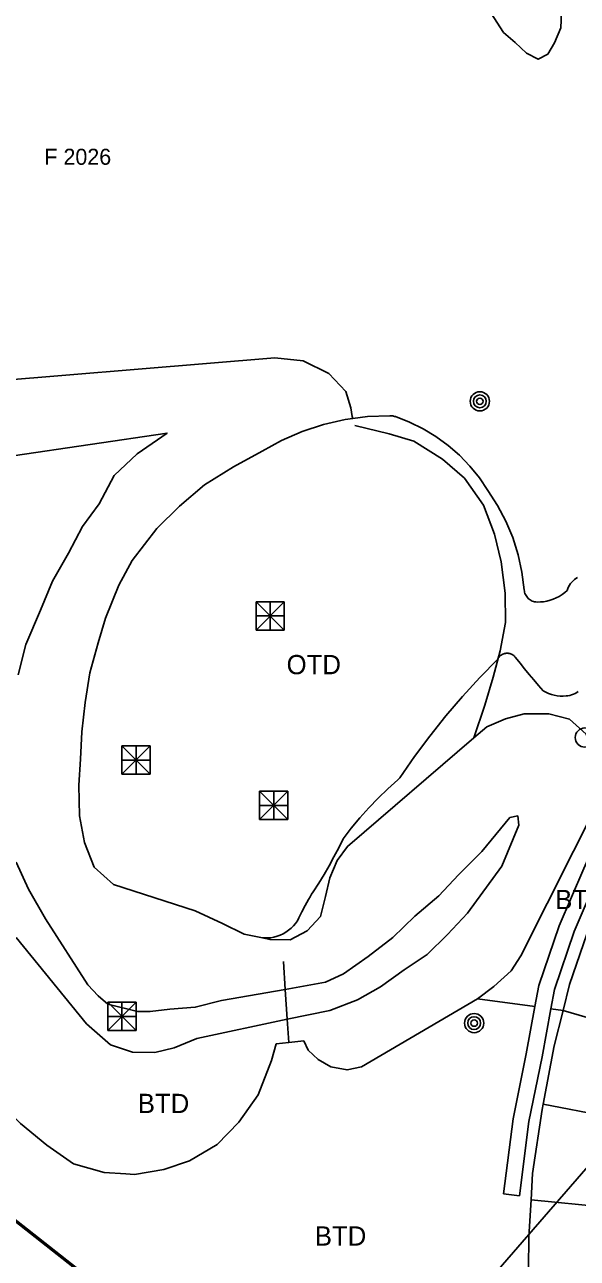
# Model space of a CAD drawing. Extents: x 198240 to 198429, y 356553 to 356721.
# Drawn here: x 198326.68 to 198343.9, y 356600.62 to 356639.08 of the extents above; entities that cross this region are included whole.
import ezdxf

# ---------------------------------------------------------------- set-up
doc = ezdxf.new("R2010")
doc.units = 0
for name, color, linetype in [('begroeid terreindeel kenmerkpunt', 7, 'Continuous'), ('BOOM', 7, 'Continuous'), ('cultuurscheiding geen IMGeo', 7, 'Continuous'), ('Duiker lijn niveau min 1', 7, 'Continuous'), ('grens individueel parkeervak', 7, 'Continuous'), ('Grens maaiveld', 7, 'Continuous'), ('kant verharding', 7, 'Continuous'), ('onbegroeid terreindeel kenmerkpunt', 7, 'Continuous'), ('Perceelnummer', 7, 'Continuous'), ('perceelsgrens_definitief', 7, 'Continuous'), ('Speelvoorziening', 7, 'Continuous')]:
    doc.layers.add(name, color=color, linetype=linetype)

msp = doc.modelspace()

# ---------------------------------------------------------------- linework, layer by layer
at = {"layer": 'BOOM'}
for centre, radius in [((198340.862, 356627.334), 0.3), ((198340.862, 356627.334), 0.2), ((198340.862, 356627.334), 0.1), ((198344.134, 356616.852), 0.3), ((198340.684, 356607.949), 0.3), ((198340.684, 356607.949), 0.2), ((198340.684, 356607.949), 0.1)]:
    msp.add_circle(centre, radius, dxfattribs=at)
at = {"layer": 'cultuurscheiding geen IMGeo'}
msp.add_lwpolyline([(198336.966, 356626.584), (198338.038, 356626.321), (198338.802, 356626.09), (198339.696, 356625.535), (198340.387, 356624.936), (198340.975, 356624.096), (198341.316, 356623.195), (198341.526, 356622.331), (198341.646, 356621.352), (198341.663, 356620.441), (198341.491, 356619.56), (198341.278, 356618.732), (198341.019, 356617.863), (198340.669, 356616.839)], dxfattribs=at)
at = {"layer": 'Duiker lijn niveau min 1'}
msp.add_lwpolyline([(198334.909, 356607.345), (198334.86, 356608.067), (198334.797, 356609), (198334.738, 356609.871)], dxfattribs=at)
at = {"layer": 'grens individueel parkeervak'}
for p, q in [((198347.785, 356607.073), (198343.457, 356608.344)), ((198347.261, 356604.556), (198342.832, 356605.425))]:
    msp.add_line(p, q, dxfattribs=at)
at = {"layer": 'Grens maaiveld'}
msp.add_line((198341.598, 356602.626), (198342.094, 356602.562), dxfattribs=at)
for points in [[(198341.203, 356639.447), (198341.598, 356638.833), (198341.961, 356638.517), (198342.319, 356638.185), (198342.68, 356638), (198342.983, 356638.157), (198343.186, 356638.51), (198343.389, 356638.974), (198343.402, 356639.466)], [(198336.899, 356626.798), (198336.881, 356626.857), (198336.843, 356627.128), (198336.681, 356627.641), (198336.15, 356628.206), (198335.359, 356628.591), (198334.475, 356628.685), (198323.691, 356627.793)], [(198336.899, 356626.798), (198336.668, 356626.767), (198335.987, 356626.612), (198335.324, 356626.394), (198334.684, 356626.116), (198334.073, 356625.779), (198333.185, 356625.294), (198332.277, 356624.73), (198331.505, 356624.068), (198330.796, 356623.364), (198330.024, 356622.371), (198329.607, 356621.601), (198329.195, 356620.573), (198328.969, 356619.801), (198328.711, 356618.869), (198328.561, 356617.945), (198328.457, 356617.025), (198328.414, 356616.174), (198328.359, 356615.367), (198328.382, 356614.413), (198328.537, 356613.584), (198328.844, 356612.812), (198329.442, 356612.27), (198331.985, 356611.454), (198332.837, 356611.057), (198333.516, 356610.723), (198334.034, 356610.613)], [(198336.899, 356626.798), (198337.36, 356626.859), (198338.057, 356626.886), (198338.087, 356626.885), (198338.116, 356626.883), (198338.146, 356626.878), (198338.175, 356626.873), (198338.204, 356626.865), (198338.233, 356626.857), (198338.671, 356626.688), (198339.093, 356626.481), (198339.495, 356626.238), (198339.875, 356625.961), (198340.228, 356625.652), (198340.554, 356625.313), (198340.848, 356624.947), (198341.109, 356624.557), (198341.414, 356624.09), (198341.674, 356623.598), (198341.889, 356623.084), (198342.057, 356622.552), (198342.175, 356622.008), (198342.244, 356621.455), (198342.249, 356621.418), (198342.257, 356621.381), (198342.268, 356621.345), (198342.283, 356621.31), (198342.3, 356621.277), (198342.321, 356621.245), (198342.345, 356621.216), (198342.371, 356621.189), (198342.399, 356621.164), (198342.43, 356621.142), (198342.463, 356621.123), (198342.497, 356621.107), (198342.532, 356621.094), (198342.569, 356621.085), (198342.606, 356621.079), (198342.644, 356621.076), (198342.747, 356621.078), (198342.85, 356621.087), (198342.952, 356621.105), (198343.052, 356621.131), (198343.15, 356621.165), (198343.245, 356621.206), (198343.336, 356621.254), (198343.423, 356621.31), (198343.506, 356621.372), (198343.583, 356621.441), (198343.603, 356621.496), (198343.627, 356621.55), (198343.655, 356621.601), (198343.688, 356621.65), (198343.725, 356621.695), (198343.766, 356621.737), (198343.81, 356621.776), (198343.857, 356621.81), (198343.907, 356621.84)], [(198347.91, 356619.599), (198346.861, 356617.91), (198345.941, 356616.427), (198344.929, 356614.639), (198344.101, 356612.773), (198343.329, 356610.981), (198342.7, 356609.121), (198342.579, 356608.462)], [(198343.93, 356618.292), (198343.881, 356618.259), (198343.83, 356618.229), (198343.777, 356618.204), (198343.722, 356618.183), (198343.666, 356618.167), (198343.608, 356618.155), (198343.55, 356618.147), (198343.457, 356618.142), (198343.364, 356618.144), (198343.272, 356618.154), (198343.18, 356618.17), (198343.091, 356618.194), (198343.003, 356618.225), (198342.918, 356618.262), (198342.836, 356618.306), (198342.689, 356618.477), (198342.544, 356618.648), (198342.399, 356618.821), (198342.256, 356618.995), (198342.114, 356619.17), (198341.973, 356619.346), (198341.956, 356619.368), (198341.938, 356619.388), (198341.917, 356619.407), (198341.895, 356619.424), (198341.872, 356619.438), (198341.847, 356619.451), (198341.821, 356619.462), (198341.795, 356619.47), (198341.768, 356619.476), (198341.74, 356619.48), (198341.712, 356619.481), (198341.685, 356619.48), (198341.657, 356619.476), (198341.63, 356619.47), (198341.604, 356619.462), (198341.578, 356619.451), (198341.553, 356619.439), (198341.53, 356619.424), (198341.508, 356619.407), (198341.487, 356619.388), (198341.468, 356619.368), (198341.451, 356619.346), (198341.436, 356619.322), (198341.424, 356619.298), (198340.864, 356618.724), (198340.323, 356618.133), (198339.802, 356617.524), (198339.302, 356616.898), (198338.822, 356616.256), (198338.364, 356615.599), (198338.355, 356615.586), (198338.346, 356615.574), (198338.336, 356615.562), (198338.325, 356615.55), (198338.314, 356615.539), (198338.302, 356615.529), (198337.991, 356615.251), (198337.69, 356614.962), (198337.4, 356614.661), (198337.122, 356614.35), (198336.856, 356614.028), (198336.602, 356613.697), (198336.462, 356613.413), (198336.316, 356613.133), (198336.164, 356612.856), (198336.006, 356612.582), (198335.841, 356612.312), (198335.671, 356612.046), (198335.62, 356611.964), (198335.57, 356611.882), (198335.521, 356611.799), (198335.416, 356611.612), (198335.317, 356611.423), (198335.224, 356611.231), (198335.174, 356611.142), (198335.116, 356611.059), (198335.051, 356610.98), (198334.979, 356610.908), (198334.901, 356610.842), (198334.818, 356610.784), (198334.73, 356610.733), (198334.638, 356610.69), (198334.542, 356610.655), (198334.444, 356610.629), (198334.344, 356610.611), (198334.242, 356610.603), (198334.141, 356610.603), (198334.034, 356610.613)], [(198348.334, 356619.335), (198347.285, 356617.646), (198346.371, 356616.173), (198345.377, 356614.413), (198344.559, 356612.573), (198343.797, 356610.801), (198343.186, 356608.995), (198343.075, 356608.396)], [(198334.034, 356610.613), (198334.325, 356610.552), (198334.946, 356610.548), (198335.482, 356610.827), (198335.892, 356611.273), (198336.053, 356611.895), (198336.185, 356612.475), (198336.413, 356613.018), (198336.736, 356613.457), (198340.669, 356616.839)], [(198311.777, 356613.258), (198312.501, 356612.688), (198316.479, 356609.557), (198334.051, 356595.726), (198335.895, 356595.044), (198338.762, 356595.561)], [(198317.199, 356612.779), (198317.336, 356612.425), (198317.386, 356612.247), (198317.407, 356612.187), (198317.895, 356611.359), (198318.614, 356610.555), (198319.52, 356610.06), (198320.357, 356609.822), (198321.201, 356609.69), (198321.995, 356609.641), (198322.783, 356609.732), (198323.445, 356609.626), (198323.947, 356609.289), (198324.35, 356608.68), (198324.73, 356607.89), (198325.01, 356607.025), (198325.417, 356606.155), (198325.926, 356605.432), (198326.545, 356604.821), (198327.369, 356604.143), (198328.198, 356603.565), (198329.158, 356603.295), (198329.827, 356603.248)], [(198342.579, 356608.462), (198342.31, 356606.993), (198341.898, 356604.966), (198341.598, 356602.626)], [(198343.075, 356608.396), (198342.8, 356606.899), (198342.392, 356604.884), (198342.094, 356602.562)]]:
    msp.add_lwpolyline(points, dxfattribs=at)
at = {"layer": 'kant verharding'}
for p, q in [((198340.786, 356608.703), (198342.579, 356608.462)), ((198343.075, 356608.396), (198343.457, 356608.344)), ((198346.896, 356602.006), (198342.457, 356602.444))]:
    msp.add_line(p, q, dxfattribs=at)
for points in [[(198321.505, 356624.931), (198331.116, 356626.341), (198330.18, 356625.694), (198329.46, 356625.018), (198328.994, 356624.142), (198328.474, 356623.436), (198328.044, 356622.603), (198327.542, 356621.727), (198327.166, 356620.82), (198326.707, 356619.748), (198326.472, 356618.803)], [(198340.669, 356616.839), (198341.075, 356617.188), (198341.657, 356617.431), (198342.242, 356617.588), (198343.015, 356617.587), (198343.659, 356617.423), (198344.172, 356616.956), (198344.514, 356616.245), (198344.663, 356615.631), (198344.6, 356614.936), (198342.14, 356610.048), (198341.84, 356609.575), (198341.293, 356609.087), (198340.786, 356608.703)], [(198334.797, 356609), (198336.055, 356609.222), (198336.61, 356609.481), (198337.38, 356610.028), (198338.15, 356610.62), (198338.837, 356611.285), (198339.584, 356611.915), (198340.198, 356612.57), (198340.919, 356613.301), (198341.801, 356614.364), (198342.043, 356614.409), (198342.079, 356614.124), (198341.551, 356612.841), (198340.472, 356611.375), (198339.854, 356610.714), (198339.217, 356610.093), (198338.503, 356609.615), (198337.767, 356609.079), (198337.047, 356608.675), (198336.183, 356608.347), (198334.86, 356608.067)], [(198326.409, 356612.966), (198326.8, 356612.127), (198327.323, 356611.203), (198328.64, 356609.147), (198328.968, 356608.803), (198329.263, 356608.535), (198330.194, 356608.311), (198330.588, 356608.308), (198331.198, 356608.38), (198331.994, 356608.445), (198332.813, 356608.651), (198334.797, 356609)], [(198343.457, 356608.344), (198343.66, 356609.157), (198344.31, 356611.059), (198344.371, 356611.203)], [(198334.86, 356608.067), (198332.041, 356607.47), (198331.335, 356607.183), (198330.731, 356607.029), (198330.038, 356607.048), (198329.354, 356607.267), (198328.604, 356607.922), (198326.409, 356610.623)], [(198340.786, 356608.703), (198337.177, 356606.583), (198336.722, 356606.489), (198336.218, 356606.581), (198335.822, 356606.818), (198335.513, 356607.109), (198335.375, 356607.4), (198334.909, 356607.345)], [(198342.832, 356605.425), (198343.18, 356607.237), (198343.457, 356608.344)], [(198334.909, 356607.345), (198334.514, 356607.299), (198334.364, 356606.779), (198333.952, 356605.716), (198333.348, 356604.857), (198332.672, 356604.168), (198331.812, 356603.658), (198331.014, 356603.384), (198330.094, 356603.229), (198329.827, 356603.248)], [(198342.457, 356602.444), (198342.503, 356603.256), (198342.799, 356605.254), (198342.832, 356605.425)], [(198341.11, 356595.383), (198342.151, 356596.522), (198342.345, 356596.889), (198342.404, 356597.244), (198342.367, 356599.296), (198342.392, 356601.284), (198342.457, 356602.444)]]:
    msp.add_lwpolyline(points, dxfattribs=at)
at = {"layer": 'perceelsgrens_definitief'}
for points in [[(198335.086, 356594.965), (198336.909, 356595.05), (198372.498, 356636.045)], [(198287.646, 356632.339), (198335.086, 356594.965)]]:
    msp.add_lwpolyline(points, dxfattribs=at)
at = {"layer": 'Speelvoorziening'}
for p, q in [((198333.887, 356621.084), (198334.767, 356621.084)), ((198333.887, 356620.204), (198333.887, 356621.084)), ((198333.887, 356621.084), (198334.767, 356620.204)), ((198333.887, 356620.204), (198334.767, 356621.084)), ((198334.327, 356621.084), (198334.327, 356620.204)), ((198334.767, 356621.084), (198334.767, 356620.204)), ((198334.767, 356620.644), (198333.887, 356620.644)), ((198334.767, 356620.204), (198333.887, 356620.204)), ((198329.709, 356616.59), (198330.589, 356616.59)), ((198329.709, 356615.71), (198329.709, 356616.59)), ((198329.709, 356616.59), (198330.589, 356615.71)), ((198329.709, 356615.71), (198330.589, 356616.59)), ((198330.149, 356616.59), (198330.149, 356615.71)), ((198330.589, 356616.59), (198330.589, 356615.71)), ((198330.589, 356616.15), (198329.709, 356616.15)), ((198330.589, 356615.71), (198329.709, 356615.71)), ((198333.999, 356615.176), (198334.879, 356615.176)), ((198333.999, 356614.296), (198333.999, 356615.176)), ((198333.999, 356615.176), (198334.879, 356614.296)), ((198333.999, 356614.296), (198334.879, 356615.176)), ((198334.439, 356615.176), (198334.439, 356614.296)), ((198334.879, 356615.176), (198334.879, 356614.296)), ((198334.879, 356614.736), (198333.999, 356614.736)), ((198334.879, 356614.296), (198333.999, 356614.296)), ((198329.266, 356608.6), (198330.146, 356608.6)), ((198329.266, 356607.72), (198329.266, 356608.6)), ((198329.266, 356608.6), (198330.146, 356607.72)), ((198329.266, 356607.72), (198330.146, 356608.6)), ((198329.706, 356608.6), (198329.706, 356607.72)), ((198330.146, 356608.6), (198330.146, 356607.72)), ((198330.146, 356608.16), (198329.266, 356608.16)), ((198330.146, 356607.72), (198329.266, 356607.72))]:
    msp.add_line(p, q, dxfattribs=at)

# ---------------------------------------------------------------- texts
at = {"layer": 'begroeid terreindeel kenmerkpunt'}
for p in [(198343.208, 356611.503), (198330.201, 356605.145), (198335.718, 356601.013)]:
    msp.add_text('BTD', height=0.6, dxfattribs=at).set_placement(p)
at = {"layer": 'onbegroeid terreindeel kenmerkpunt'}
msp.add_text('OTD', height=0.6, dxfattribs=at).set_placement((198334.839, 356618.826))
at = {"layer": 'Perceelnummer'}
msp.add_text('F 2026', height=0.5, dxfattribs=at).set_placement((198327.29, 356634.708))

doc.saveas('drawing.dxf')
